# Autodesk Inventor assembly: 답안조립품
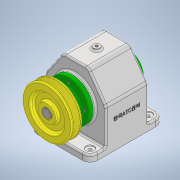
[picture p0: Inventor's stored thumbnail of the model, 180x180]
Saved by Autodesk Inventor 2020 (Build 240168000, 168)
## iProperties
Created: 2022-12
Part Number: 답안조립품
Document SubType Name: Assembly
Designer: 1강의실14
Author: 1강의실14
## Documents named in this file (15)
- C:\Users\1강의실14\Desktop\721206V1012\답안조립품.iam
- C:\Users\1강의실14\Desktop\721206V1012\본체.ipt
- C:\Users\1강의실14\Desktop\721206V1012\V-벨트풀리.ipt
- C:\Users\1강의실14\Desktop\721206V1012\뒤커버.ipt
- C:\Users\1강의실14\Desktop\721206V1012\멈춤나사 - M4x10.ipt
- C:\Users\1강의실14\Desktop\721206V1012\베어링 6203.ipt
- C:\Users\1강의실14\Desktop\721206V1012\볼트 M3 x 8.ipt
- C:\Users\1강의실14\Desktop\721206V1012\볼트 M3 x 10.ipt
- C:\Users\1강의실14\Desktop\721206V1012\스퍼기어.ipt
- C:\Users\1강의실14\Desktop\721206V1012\앞커버.ipt
- C:\Users\1강의실14\Desktop\721206V1012\오일 실 17 x 32 x 8.ipt
- C:\Users\1강의실14\Desktop\721206V1012\축.ipt
- C:\Users\1강의실14\Desktop\721206V1012\칼라.ipt
- C:\Users\1강의실14\Desktop\721206V1012\키 - 5 x 5 x 18.ipt
- C:\Users\1강의실14\Desktop\721206V1012\키 - 6 x 6 x 22.ipt
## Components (9 placed, 3 different names)
1. V-벨트풀리:1
2. ISO 4762 M3 x 10:1 — 각도:5
3. ISO 4762 M3 x 10:2
4. ISO 4762 M3 x 10:3
5. ISO 4762 M3 x 10:4
6. ISO 4762 M3 x 8:1 — 각도:4
7. ISO 4762 M3 x 8:2
8. ISO 4762 M3 x 8:3
9. ISO 4762 M3 x 8:4
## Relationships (2: Angle 2)
- 각도:4 [Angle]: ISO 4762 M3 x 8:1
- 각도:5 [Angle]: ISO 4762 M3 x 10:1
